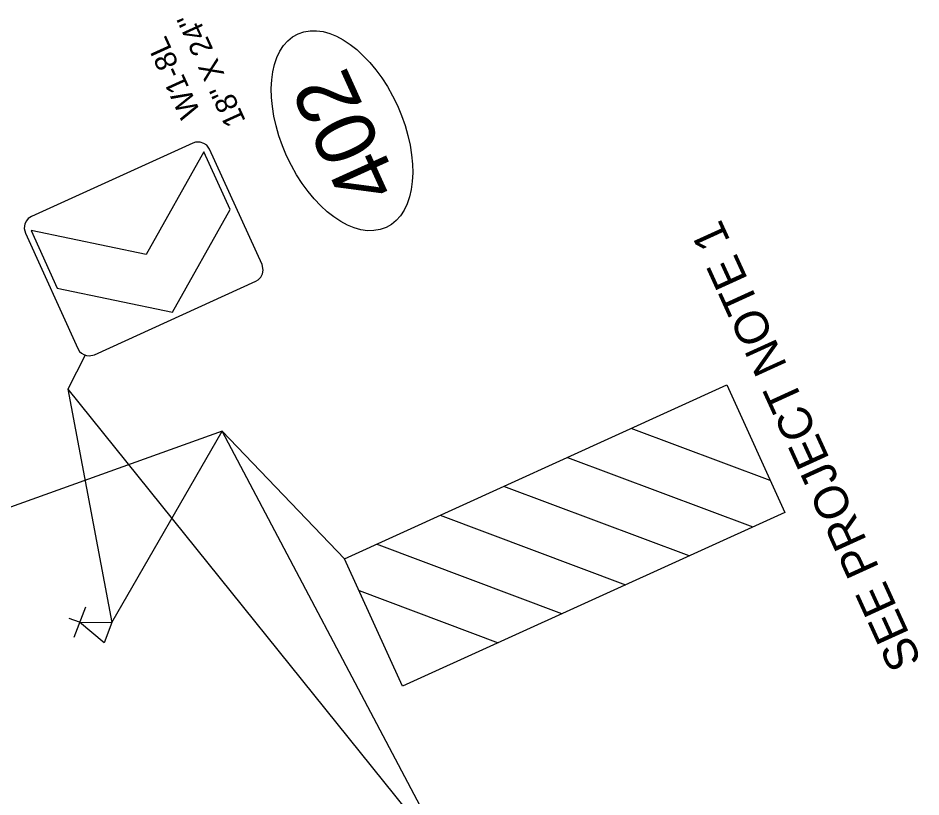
# Model space of a CAD drawing. Extents: x 2096999 to 2102576, y 682920 to 687015.
# Drawn here: x 2102279.3 to 2102467.5, y 683671.5 to 683833.8 of the extents above; entities that cross this region are included whole.
import ezdxf

# ---------------------------------------------------------------- set-up
doc = ezdxf.new("R2010")
doc.units = 0
doc.layers.add('Default', color=7, linetype='Continuous')

msp = doc.modelspace()

# ---------------------------------------------------------------- linework, layer by layer
at = {"layer": 'Default'}
for p, q in [((2102306.04, 683784.52), (2102306.04, 683784.52)), ((2102347.38, 683721.13), (2102427.04, 683757.37)), ((2102427.04, 683757.37), (2102439.11, 683730.81)), ((2102289.71, 683756.5), (2102298.88, 683707.86)), ((2102321.86, 683747.72), (2102244.12, 683719.84)), ((2102298.88, 683707.86), (2102321.86, 683747.72)), ((2102347.38, 683721.13), (2102321.86, 683747.72)), ((2102370.07, 683656.59), (2102321.86, 683747.72)), ((2102436.1, 683737.45), (2102407.12, 683748.31)), ((2102393.84, 683742.27), (2102432.48, 683727.79)), ((2102419.2, 683721.75), (2102380.57, 683736.23)), ((2102439.11, 683730.81), (2102359.45, 683694.58)), ((2102367.29, 683730.19), (2102405.92, 683715.72)), ((2102392.65, 683709.68), (2102354.01, 683724.15)), ((2102359.45, 683694.58), (2102347.38, 683721.13)), ((2102350.4, 683714.5), (2102379.37, 683703.64)), ((2102293.38, 683711.08), (2102290.93, 683704.74)), ((2102292.14, 683707.89), (2102289.99, 683708.72)), ((2102297.23, 683703.6), (2102292.14, 683707.89)), ((2102292.14, 683707.89), (2102298.88, 683707.86)), ((2102298.88, 683707.86), (2102297.23, 683703.6))]:
    msp.add_line(p, q, dxfattribs=at)
for points in [[(2102315.74, 683807.78), (2102282.13, 683792.49), (2102281.41, 683792.02), (2102281.05, 683791.58), (2102280.73, 683790.92), (2102280.6, 683789.94), (2102280.82, 683788.99), (2102291.74, 683764.98), (2102292.14, 683764.35), (2102292.53, 683764), (2102293.01, 683763.71), (2102293.57, 683763.5), (2102294.11, 683763.44), (2102295.23, 683763.67), (2102328.85, 683778.96), (2102329.37, 683779.25), (2102329.91, 683779.84), (2102330.25, 683780.53), (2102330.4, 683781.31), (2102330.16, 683782.46), (2102319.24, 683806.47), (2102318.64, 683807.31), (2102318.05, 683807.71), (2102317.27, 683807.99), (2102316.32, 683807.93), (2102315.74, 683807.78)], [(2102293.29, 683763.6), (2102289.71, 683756.5), (2102370.07, 683656.59)]]:
    msp.add_lwpolyline(points, dxfattribs=at)
msp.add_lwpolyline([(2102318.05, 683805.93), (2102306.04, 683784.52), (2102282.03, 683789.54), (2102287.49, 683777.54), (2102311.5, 683772.51), (2102323.51, 683793.92)], close=True, dxfattribs=at)
msp.add_ellipse((2102346.83, 683810.35), major_axis=(9.17, -20.19), ratio=0.571429, dxfattribs=at)

# ---------------------------------------------------------------- texts
for s, height, rotation, p in [("18'' X 24''", 4.5, 114.458, (2102326.83, 683812.37)), ('W1-8L', 4.5, 114.458, (2102317.41, 683814.19)), ('402', 12.516, 114.4239, (2102359.01, 683798.64)), ('SEE PROJECT NOTE 1', 7, 114.4888, (2102467.75, 683699.81))]:
    msp.add_text(s, height=height, rotation=rotation, dxfattribs=at).set_placement(p)

doc.saveas('drawing.dxf')
